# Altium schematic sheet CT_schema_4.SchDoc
size 229 x 200 mm
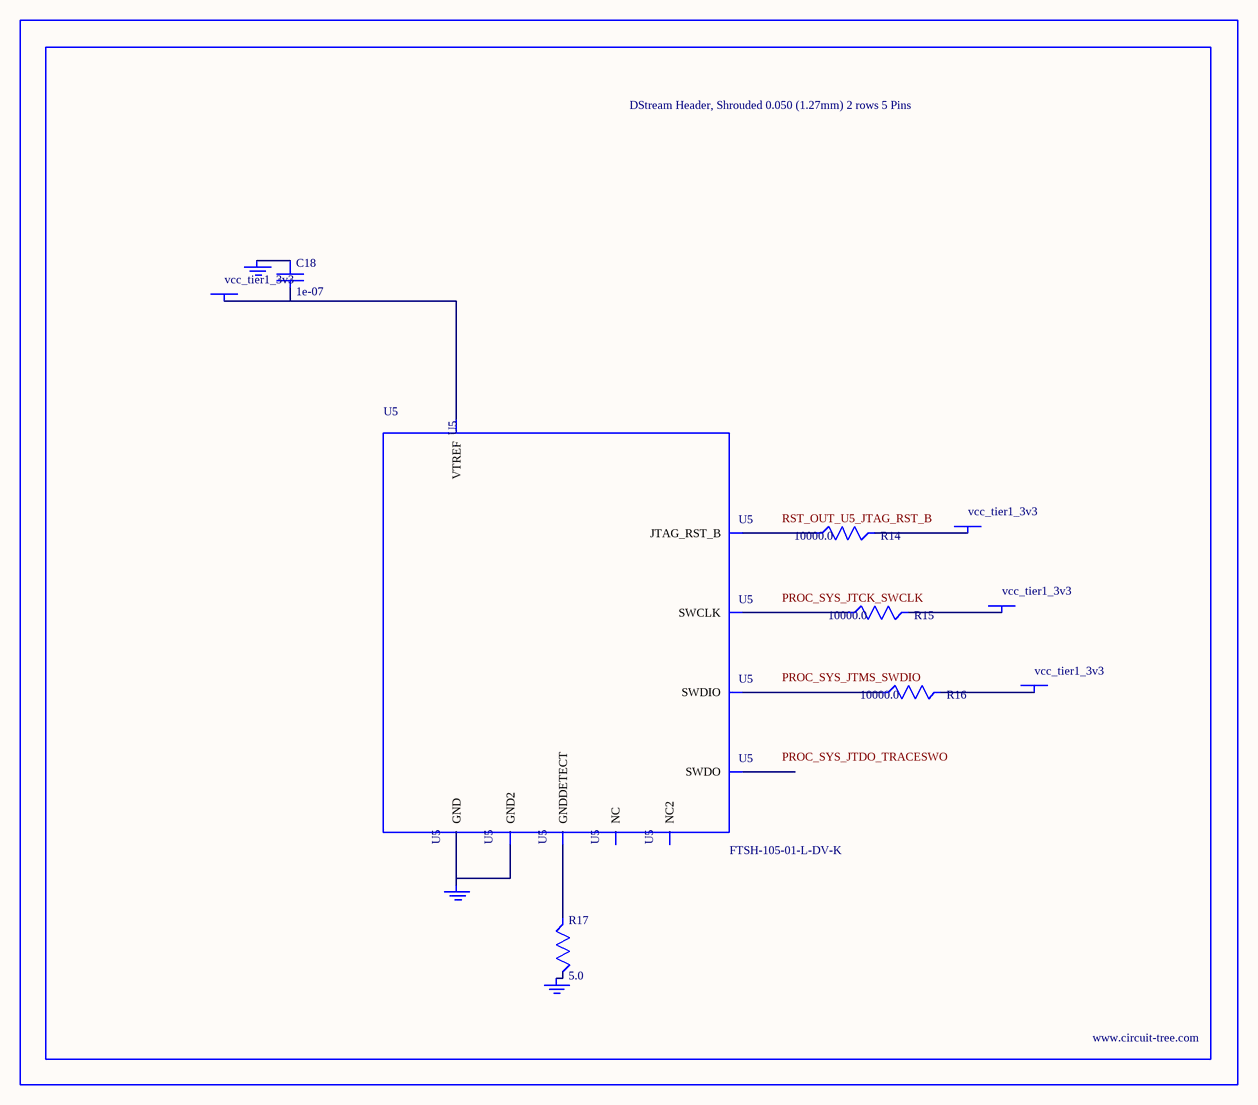
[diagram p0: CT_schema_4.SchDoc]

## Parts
BORDER3  (no value)
C18  1e-07  [C0402]
GND_INSTANCE_3_0  (no value)
GND_INSTANCE_3_1  (no value)
GND_INSTANCE_3_2  (no value)
POWER_INSTANCE_3_0  vcc_tier1_3v3
POWER_INSTANCE_3_1  vcc_tier1_3v3
POWER_INSTANCE_3_2  vcc_tier1_3v3
POWER_INSTANCE_3_3  vcc_tier1_3v3
R14  10000.0  [R0603]
R15  10000.0  [R0603]
R16  10000.0  [R0603]
R17  5.0  [R0603]
U5  FTSH-105-01-L-DV-K  [SAMTEC_FTSH-105-01-L-DV-K]

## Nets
NetC18_1: C18.1 GND_INSTANCE_3_0.0(GND)
NetC18_2: C18.2 POWER_INSTANCE_3_0.0(PWR) U5.1(VTREF)
NetGND_INSTANCE_3_1_0: GND_INSTANCE_3_1.0(GND) R17.2
NetGND_INSTANCE_3_2_0: GND_INSTANCE_3_2.0(GND) U5.3(GND) U5.5(GND2)
NetPOWER_INSTANCE_3_1_0: POWER_INSTANCE_3_1.0(PWR) R16.2
NetPOWER_INSTANCE_3_2_0: POWER_INSTANCE_3_2.0(PWR) R15.2
NetPOWER_INSTANCE_3_3_0: POWER_INSTANCE_3_3.0(PWR) R14.2
NetR14_1: R14.1 U5.10(JTAG_RST_B)
NetR15_1: R15.1 U5.4(SWCLK)
NetR16_1: R16.1 U5.2(SWDIO)
NetR17_1: R17.1 U5.9(GNDDETECT)

Not connected (* = marked no-connect by the designer): U5 6(SWDO) 7(NC) 8(NC2)

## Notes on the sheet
- Labels drawn without touching a wire or pin: PROC_SYS_JTCK_SWCLK, PROC_SYS_JTDO_TRACESWO, PROC_SYS_JTMS_SWDIO, RST_OUT_U5_JTAG_RST_B

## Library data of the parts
BORDER3 = BORDER_PAGE3
C18 = C0402C104K3RACTU
GND_INSTANCE_3_0-GND_INSTANCE_3_2 = GND
POWER_INSTANCE_3_0-POWER_INSTANCE_3_3 = PWR
R14-R16 = RC0603JR-0710KL
R17 = ERJ-3GEYJ5R1V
